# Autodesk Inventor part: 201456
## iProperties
Created: 2007-10
Part Number: 201456
Document SubType Name: Modeling
Designer: TT
Density: 7.85 g/cm^3
Mass: 599.106 g
Surface Area: 203.247 cm^2
Volume: 76.3193 cm^3
Material: Steel
Description: HOR SUPPORT BAR
Component Category: Lower Component
Author: TT
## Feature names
1. Revolution1
2. Chamfer1
3. Fillet1
